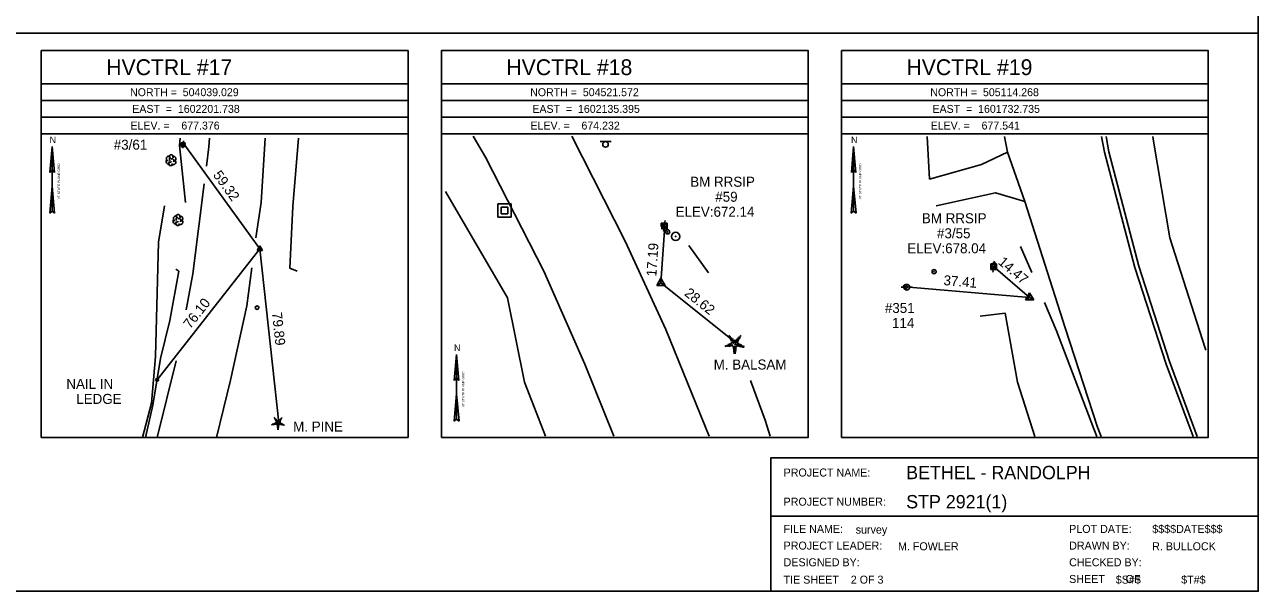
# Model space of a CAD drawing. Extents: x 1598730 to 1599370, y 501440 to 502728.
# Drawn here: x 1598999.5 to 1599369.5, y 501873 to 502042.9 of the extents above; entities that cross this region are included whole.
import ezdxf

# ---------------------------------------------------------------- set-up
doc = ezdxf.new("R2010")
doc.units = 0
for name, color, linetype in [('C_C', 7, 'Continuous'), ('CBP', 7, 'Continuous'), ('CPBM', 7, 'Continuous'), ('CPSM', 7, 'Continuous'), ('Default', 7, 'Continuous'), ('DS', 7, 'Continuous'), ('L_C', 7, 'Continuous'), ('LABL', 7, 'Continuous'), ('LARO', 7, 'Continuous'), ('LAWA', 7, 'Continuous'), ('LFNC', 7, 'Continuous'), ('LTC', 7, 'Continuous'), ('LTD', 7, 'Continuous'), ('MPIR', 7, 'Continuous'), ('NBL1', 7, 'Continuous'), ('NBL2', 7, 'Continuous'), ('NNA_P', 7, 'Continuous'), ('PET', 7, 'Continuous'), ('RDG', 7, 'Continuous'), ('RDP', 7, 'Continuous'), ('RGP', 7, 'Continuous'), ('RGR', 7, 'Continuous'), ('SSGN', 7, 'Continuous'), ('U_C', 7, 'Continuous'), ('UP', 7, 'Continuous'), ('UPGW', 7, 'Continuous'), ('UTMH', 7, 'Continuous')]:
    doc.layers.add(name, color=color, linetype=linetype)

msp = doc.modelspace()

# ---------------------------------------------------------------- linework, layer by layer
at = {"layer": 'CBP'}
for centre, radius in [((1599047.25, 502007.23), 0.41), ((1599047.25, 502007.23), 0.0547), ((1599191.49, 501982.63), 0.625), ((1599191.49, 501982.63), 0.0833), ((1599289.96, 501970.55), 0.625), ((1599289.96, 501970.55), 0.0833), ((1599263.66, 501964.32), 0.625), ((1599263.66, 501964.32), 0.0833), ((1599212.73, 501947.63), 0.625), ((1599212.73, 501947.63), 0.0833), ((1599039.25, 501936.41), 0.41), ((1599039.25, 501936.41), 0.0547), ((1599075.78, 501923.58), 0.41), ((1599075.78, 501923.58), 0.0547)]:
    msp.add_circle(centre, radius, dxfattribs=at)
at = {"layer": 'CPBM'}
for p, q in [((1599190.44, 501982.37), (1599190.44, 501983.37)), ((1599190.44, 501983.37), (1599191.44, 501983.37)), ((1599191.44, 501983.37), (1599191.44, 501982.37)), ((1599191.44, 501982.37), (1599190.44, 501982.37)), ((1599190.94, 501982.87), (1599190.94, 501982.87)), ((1599190.94, 501982.87), (1599190.94, 501982.87)), ((1599289.8, 501970.38), (1599289.8, 501971.38)), ((1599289.8, 501971.38), (1599290.8, 501971.38)), ((1599290.8, 501970.38), (1599289.8, 501970.38)), ((1599290.31, 501970.88), (1599290.31, 501970.88)), ((1599290.31, 501970.88), (1599290.31, 501970.88)), ((1599290.8, 501971.38), (1599290.8, 501970.38)), ((1599075.46, 501923.34), (1599075.46, 501923.99)), ((1599075.46, 501923.99), (1599076.12, 501923.99)), ((1599076.12, 501923.34), (1599075.46, 501923.34)), ((1599075.79, 501923.66), (1599075.79, 501923.66)), ((1599075.79, 501923.66), (1599075.79, 501923.66)), ((1599076.12, 501923.99), (1599076.12, 501923.34))]:
    msp.add_line(p, q, dxfattribs=at)
at = {"layer": 'CPSM'}
for p, q in [((1599069.25, 501975.22), (1599070.07, 501976.64)), ((1599070.89, 501975.22), (1599070.07, 501976.64)), ((1599070.07, 501975.69), (1599070.07, 501976.64)), ((1599069.25, 501975.22), (1599070.07, 501975.69)), ((1599069.25, 501975.22), (1599070.89, 501975.22)), ((1599070.07, 501975.69), (1599070.07, 501975.69)), ((1599070.07, 501975.69), (1599070.89, 501975.22)), ((1599189.11, 501964.75), (1599190.36, 501966.92)), ((1599189.11, 501964.75), (1599190.36, 501965.47)), ((1599189.11, 501964.75), (1599191.61, 501964.75)), ((1599191.61, 501964.75), (1599190.36, 501966.92)), ((1599190.36, 501965.47), (1599190.36, 501966.92)), ((1599190.36, 501965.47), (1599190.36, 501965.47)), ((1599190.36, 501965.47), (1599191.61, 501964.75)), ((1599299.69, 501960.39), (1599300.94, 501962.56)), ((1599299.69, 501960.39), (1599300.94, 501961.11)), ((1599302.19, 501960.39), (1599300.94, 501962.56)), ((1599300.94, 501961.11), (1599300.94, 501962.56)), ((1599300.94, 501961.11), (1599300.94, 501961.11)), ((1599300.94, 501961.11), (1599302.19, 501960.39)), ((1599299.69, 501960.39), (1599302.19, 501960.39))]:
    msp.add_line(p, q, dxfattribs=at)
at = {"layer": 'Default'}
for p, q in [((1599070.07, 501975.69), (1599047.25, 502007.23)), ((1599190.36, 501965.47), (1599191.49, 501982.63)), ((1599070.07, 501975.69), (1599039.25, 501936.41)), ((1599075.78, 501923.58), (1599070.07, 501975.69)), ((1599300.94, 501961.11), (1599289.96, 501970.55)), ((1599212.73, 501947.63), (1599190.36, 501965.47)), ((1599263.66, 501964.32), (1599300.94, 501961.11))]:
    msp.add_line(p, q, dxfattribs=at)
at = {"layer": 'DS'}
for p, q in [((1599141.47, 501989.17), (1599145.47, 501989.17)), ((1599141.47, 501985.17), (1599141.47, 501989.17)), ((1599142.47, 501986.17), (1599142.47, 501988.17)), ((1599142.47, 501988.17), (1599144.47, 501988.17)), ((1599143.47, 501987.17), (1599143.47, 501987.17)), ((1599143.47, 501987.17), (1599143.47, 501987.17)), ((1599144.47, 501988.17), (1599144.47, 501986.17)), ((1599145.47, 501989.17), (1599145.47, 501985.17)), ((1599145.47, 501985.17), (1599141.47, 501985.17)), ((1599144.47, 501986.17), (1599142.47, 501986.17))]:
    msp.add_line(p, q, dxfattribs=at)
at = {"layer": 'LABL'}
for points in [[(1599047.82, 501989.57), (1599045.99, 502006.66), (1599046.18, 502008.9)], [(1599302.46, 501919.47), (1599297.26, 501935.71), (1599293.6, 501956.43), (1599286.07, 501955.55)]]:
    msp.add_lwpolyline(points, dxfattribs=at)
at = {"layer": 'LARO'}
msp.add_lwpolyline([(1599035.77, 501919.18), (1599037.98, 501928.82), (1599040.31, 501942.87), (1599043.1, 501954.27), (1599045.76, 501969), (1599044.87, 501969.59)], dxfattribs=at)
at = {"layer": 'LAWA'}
for points in [[(1599353.82, 501945.32), (1599353.58, 501945.95), (1599343, 501979.03), (1599338.14, 502008.01), (1599337.86, 502009.44)], [(1599155.76, 501919.52), (1599149.43, 501935.77), (1599144.39, 501961.06), (1599125.75, 501992.92)], [(1599034.84, 501919.18), (1599037.58, 501929.42), (1599038.81, 501943.43), (1599039.71, 501977.67), (1599041.45, 501988.65)], [(1599204.63, 501968.54), (1599198.73, 501976.75)], [(1599223.16, 501919.52), (1599221.59, 501924.37), (1599217.24, 501936.19)]]:
    msp.add_lwpolyline(points, dxfattribs=at)
at = {"layer": 'LFNC'}
msp.add_lwpolyline([(1599081.27, 501969.02), (1599079.06, 501969.92), (1599079.93, 501988.37), (1599081.63, 502008.9)], dxfattribs=at)
at = {"layer": 'LTC'}
for p, q in [((1599209.66, 501946.75), (1599209.82, 501946.29)), ((1599210.12, 501946.97), (1599210.33, 501946.32)), ((1599210.58, 501947.19), (1599210.85, 501946.35)), ((1599210.63, 501949.47), (1599210.99, 501949.73)), ((1599210.84, 501949.01), (1599211.37, 501949.39)), ((1599211.03, 501947.4), (1599211.36, 501946.38)), ((1599211.05, 501948.54), (1599211.75, 501949.05)), ((1599211.26, 501948.08), (1599212.14, 501948.72)), ((1599211.49, 501947.62), (1599212.5, 501948.36)), ((1599211.49, 501947.62), (1599211.87, 501946.43)), ((1599213.1, 501946.43), (1599211.87, 501946.43)), ((1599212.5, 501948.36), (1599213.49, 501947.63)), ((1599212.92, 501948.67), (1599213.73, 501948.08)), ((1599213.49, 501947.63), (1599213.1, 501946.43)), ((1599213.29, 501949.02), (1599213.97, 501948.52)), ((1599213.93, 501947.36), (1599213.59, 501946.32)), ((1599213.66, 501949.37), (1599214.21, 501948.97)), ((1599214.03, 501949.71), (1599214.45, 501949.41)), ((1599214.38, 501947.11), (1599214.09, 501946.23)), ((1599214.82, 501946.86), (1599214.58, 501946.13)), ((1599215.26, 501946.61), (1599215.08, 501946.04)), ((1599213.06, 501945.93), (1599211.92, 501945.93)), ((1599212.98, 501945.43), (1599211.99, 501945.43)), ((1599212.9, 501944.93), (1599212.07, 501944.93)), ((1599212.81, 501944.43), (1599212.14, 501944.43)), ((1599074.31, 501924.95), (1599074.54, 501925.12)), ((1599074.45, 501924.65), (1599074.79, 501924.9)), ((1599074.58, 501924.34), (1599075.05, 501924.68)), ((1599074.72, 501924.04), (1599075.3, 501924.45)), ((1599074.87, 501923.74), (1599075.53, 501924.22)), ((1599075.53, 501924.22), (1599076.19, 501923.74)), ((1599075.81, 501924.42), (1599076.34, 501924.04)), ((1599076.05, 501924.65), (1599076.5, 501924.33)), ((1599076.29, 501924.88), (1599076.66, 501924.62)), ((1599076.54, 501925.11), (1599076.81, 501924.91)), ((1599073.67, 501923.17), (1599073.77, 501922.86)), ((1599073.97, 501923.31), (1599074.11, 501922.88)), ((1599074.27, 501923.45), (1599074.45, 501922.9)), ((1599074.57, 501923.59), (1599074.79, 501922.92)), ((1599074.87, 501923.74), (1599075.12, 501922.95)), ((1599075.93, 501922.95), (1599075.12, 501922.95)), ((1599075.9, 501922.63), (1599075.15, 501922.63)), ((1599075.85, 501922.3), (1599075.2, 501922.3)), ((1599075.79, 501921.97), (1599075.25, 501921.97)), ((1599075.74, 501921.64), (1599075.3, 501921.64)), ((1599076.19, 501923.74), (1599075.93, 501922.95)), ((1599076.47, 501923.57), (1599076.25, 501922.88)), ((1599076.77, 501923.4), (1599076.58, 501922.82)), ((1599077.06, 501923.24), (1599076.9, 501922.76)), ((1599077.35, 501923.07), (1599077.23, 501922.7))]:
    msp.add_line(p, q, dxfattribs=at)
at = {"layer": 'LTD'}
for p, q in [((1599043.4, 502002.32), (1599043.4, 502002.32)), ((1599043.4, 502002.32), (1599043.4, 502002.32)), ((1599045.49, 501984.38), (1599045.49, 501984.38)), ((1599045.49, 501984.38), (1599045.49, 501984.38))]:
    msp.add_line(p, q, dxfattribs=at)
for centre in [(1599043.43, 502003.26), (1599045.52, 501985.32)]:
    msp.add_arc(centre, 0.687, 335.5272, 180.9563, dxfattribs=at)
for centre, major_axis, ratio, start_param, end_param in [((1599042.68, 502001.86), (0.383, -0.683), 0.959034, 3.141593, 6.283185), ((1599042.88, 502002.76), (0.794, -0.336), 0.895232, 1.570796, 4.712389), ((1599043.09, 502001.83), (-0.41, -0.055), 0.423636, 0, 3.141593), ((1599043.26, 502002.62), (-0.137, -0.519), 0.645439, 3.141593, 6.283185), ((1599043.72, 502002.21), (-0.328, 0.437), 0.989748, 3.141593, 6.283185), ((1599044.05, 502001.78), (-0.715, 0.52), 0.841452, 1.570796, 4.712389), ((1599044.08, 502002.71), (-0.748, -0.317), 0.949671, 1.570796, 4.712389), ((1599043.4, 502001.34), (0.174, 0.696), 0.942809, 1.570796, 4.712389), ((1599044.78, 501983.91), (0.383, -0.683), 0.959034, 3.141593, 6.283185), ((1599044.97, 501984.81), (0.794, -0.336), 0.895232, 1.570796, 4.712389), ((1599045.49, 501983.39), (0.174, 0.696), 0.942809, 1.570796, 4.712389), ((1599045.19, 501983.89), (-0.41, -0.055), 0.423636, 0, 3.141593), ((1599045.35, 501984.68), (-0.137, -0.519), 0.645439, 3.141593, 6.283185), ((1599045.82, 501984.27), (-0.328, 0.437), 0.989748, 3.141593, 6.283185), ((1599046.15, 501983.83), (-0.715, 0.52), 0.841452, 1.570796, 4.712389), ((1599046.17, 501984.76), (-0.748, -0.317), 0.949671, 1.570796, 4.712389)]:
    msp.add_ellipse(centre, major_axis=major_axis, ratio=ratio, start_param=start_param, end_param=end_param, dxfattribs=at)
at = {"layer": 'MPIR'}
for radius in [0.625, 0.0833]:
    msp.add_circle((1599192.37, 501980.8), radius, dxfattribs=at)
at = {"layer": 'NBL1'}
msp.add_line((1599223.28, 501895.51), (1599369.53, 501895.51), dxfattribs=at)
msp.add_lwpolyline([(1598729.53, 501873.01), (1599369.53, 501873.01), (1599369.53, 502293.01), (1598729.53, 502293.01)], close=True, dxfattribs=at)
msp.add_lwpolyline([(1599369.53, 501913.01), (1599223.28, 501913.01), (1599223.28, 501873.01)], dxfattribs=at)
at = {"layer": 'NBL2'}
for p, q in [((1598729.53, 502040.34), (1599369.53, 502040.34)), ((1599114.53, 502025.18), (1599004.53, 502025.18)), ((1599234.53, 502025.18), (1599124.53, 502025.18)), ((1599354.53, 502025.18), (1599244.53, 502025.18)), ((1599114.53, 502020.18), (1599004.53, 502020.18)), ((1599234.53, 502020.18), (1599124.53, 502020.18)), ((1599354.53, 502020.18), (1599244.53, 502020.18)), ((1599114.53, 502015.18), (1599004.53, 502015.18)), ((1599234.53, 502015.18), (1599124.53, 502015.18)), ((1599354.53, 502015.18), (1599244.53, 502015.18)), ((1599114.53, 502010.18), (1599004.53, 502010.18)), ((1599234.53, 502010.18), (1599124.53, 502010.18)), ((1599354.53, 502010.18), (1599244.53, 502010.18))]:
    msp.add_line(p, q, dxfattribs=at)
for points in [[(1599004.53, 501919.18), (1599114.53, 501919.18), (1599114.53, 502035.18), (1599004.53, 502035.18)], [(1599124.53, 501919.18), (1599234.53, 501919.18), (1599234.53, 502035.18), (1599124.53, 502035.18)], [(1599244.53, 501919.18), (1599354.53, 501919.18), (1599354.53, 502035.18), (1599244.53, 502035.18)]]:
    msp.add_lwpolyline(points, close=True, dxfattribs=at)
at = {"layer": 'NNA_P'}
for p, q in [((1599007.09, 501998.59), (1599007.79, 502006.38)), ((1599007.79, 501987.01), (1599007.79, 502006.38)), ((1599008.48, 501998.59), (1599007.79, 502006.38)), ((1599247.47, 501998.59), (1599248.16, 502006.38)), ((1599248.16, 501987.01), (1599248.16, 502006.38)), ((1599248.85, 501998.59), (1599248.16, 502006.38)), ((1599007.09, 501998.59), (1599007.79, 501999.36)), ((1599008.48, 501998.59), (1599007.79, 501999.36)), ((1599247.47, 501998.59), (1599248.16, 501999.36)), ((1599248.86, 501998.59), (1599248.16, 501999.36)), ((1599007.79, 501994.53), (1599007.07, 501986.37)), ((1599007.79, 501994.53), (1599008.51, 501986.37)), ((1599248.16, 501994.53), (1599247.44, 501986.37)), ((1599248.16, 501994.53), (1599248.88, 501986.37)), ((1599007.79, 501987.01), (1599007.07, 501986.37)), ((1599007.79, 501987.01), (1599008.51, 501986.37)), ((1599248.16, 501987.01), (1599247.44, 501986.37)), ((1599248.16, 501987.01), (1599248.88, 501986.37)), ((1599128.39, 501936.25), (1599129.08, 501944.04)), ((1599129.09, 501924.67), (1599129.08, 501944.04)), ((1599129.78, 501936.25), (1599129.08, 501944.04)), ((1599128.39, 501936.25), (1599129.09, 501937.02)), ((1599129.78, 501936.25), (1599129.09, 501937.02)), ((1599129.09, 501932.2), (1599128.37, 501924.03)), ((1599129.09, 501932.2), (1599129.81, 501924.03)), ((1599129.09, 501924.67), (1599128.37, 501924.03)), ((1599129.09, 501924.67), (1599129.81, 501924.03))]:
    msp.add_line(p, q, dxfattribs=at)
at = {"layer": 'PET'}
for points in [[(1599176.24, 501919.52), (1599167.53, 501941.08), (1599155.21, 501968.99), (1599137.74, 502003.21), (1599134.05, 502009.54)], [(1599204.78, 501919.52), (1599191.87, 501951.52), (1599179.61, 501977.97), (1599163.65, 502009.54)], [(1599322.37, 501919.47), (1599321.26, 501922.28), (1599311.63, 501952.05), (1599299.52, 501989.9), (1599294.3, 502004.65), (1599293.36, 502009.44)], [(1599349.95, 501919.47), (1599341.87, 501941.13), (1599332.53, 501970.1), (1599323.4, 502004.7), (1599322.52, 502009.44)], [(1599054.08, 502000.54), (1599054.81, 502006.3), (1599054.99, 502008.9)], [(1599068.87, 501979.06), (1599070.43, 501989.61), (1599071.62, 502008.9)], [(1599047.94, 501957.45), (1599050.01, 501968.19), (1599053.41, 501995.17)], [(1599057.11, 501919.18), (1599061.31, 501936.33), (1599066.19, 501958.65), (1599067.63, 501970.03)], [(1599039.32, 501919.18), (1599044.98, 501942.11)]]:
    msp.add_lwpolyline(points, dxfattribs=at)
at = {"layer": 'RDG'}
msp.add_lwpolyline([(1599270.87, 501996.64), (1599270.22, 502009.44)], dxfattribs=at)
at = {"layer": 'RDP'}
for points in [[(1599270.87, 501996.64), (1599286.53, 502000.97), (1599294.3, 502004.65)], [(1599299.52, 501989.9), (1599290.7, 501992.53), (1599272.91, 501988.61)]]:
    msp.add_lwpolyline(points, dxfattribs=at)
at = {"layer": 'RGP'}
msp.add_line((1599194.79, 501979.43), (1599194.79, 501979.43), dxfattribs=at)
for radius in [1.25, 0.0833]:
    msp.add_circle((1599194.79, 501979.43), radius, dxfattribs=at)
at = {"layer": 'RGR'}
for points in [[(1599351.17, 501919.47), (1599342.89, 501941.89), (1599333.65, 501970.56), (1599324.73, 502004.82), (1599323.88, 502009.44)], [(1599301.59, 501968.61), (1599298.24, 501976.45)], [(1599321.1, 501919.47), (1599320.22, 501921.72), (1599309.05, 501951.14), (1599305.44, 501959.59)]]:
    msp.add_lwpolyline(points, dxfattribs=at)
at = {"layer": 'SSGN'}
for p, q in [((1599172.11, 502007.86), (1599175.44, 502007.86)), ((1599173.75, 502007.03), (1599173.75, 502007.03))]:
    msp.add_line(p, q, dxfattribs=at)
msp.add_circle((1599173.75, 502007.03), 0.833, dxfattribs=at)
at = {"layer": 'UP'}
for p, q in [((1599046.5, 502006.42), (1599046.5, 502007.51)), ((1599046.5, 502007.51), (1599047.6, 502007.51)), ((1599047.6, 502006.42), (1599046.5, 502006.42)), ((1599046.89, 502005.87), (1599047.05, 502006.42)), ((1599047.21, 502008.06), (1599047.05, 502007.51)), ((1599047.05, 502006.97), (1599047.05, 502006.97)), ((1599047.6, 502007.51), (1599047.6, 502006.42)), ((1599190.6, 501981.75), (1599190.6, 501983.42)), ((1599190.6, 501983.42), (1599192.26, 501983.42)), ((1599191.68, 501984.25), (1599191.43, 501983.42)), ((1599192.26, 501983.42), (1599192.26, 501981.75)), ((1599192.26, 501981.75), (1599190.6, 501981.75)), ((1599191.18, 501980.92), (1599191.43, 501981.75)), ((1599191.43, 501982.59), (1599191.43, 501982.59)), ((1599289.3, 501969.5), (1599289.3, 501971.17)), ((1599289.3, 501971.17), (1599290.97, 501971.17)), ((1599290.97, 501969.5), (1599289.3, 501969.5)), ((1599289.88, 501968.67), (1599290.13, 501969.5)), ((1599290.38, 501972), (1599290.13, 501971.17)), ((1599290.13, 501970.34), (1599290.13, 501970.34)), ((1599290.97, 501971.17), (1599290.97, 501969.5)), ((1599262.44, 501964.2), (1599263.26, 501964.2)), ((1599264.1, 501964.2), (1599264.1, 501964.2)), ((1599265.76, 501964.2), (1599264.93, 501964.2)), ((1599264.93, 501964.2), (1599264.93, 501964.2)), ((1599265.76, 501964.2), (1599265.76, 501964.2))]:
    msp.add_line(p, q, dxfattribs=at)
for centre, radius in [((1599047.05, 502006.97), 0.547), ((1599191.43, 501982.59), 0.833), ((1599290.13, 501970.34), 0.833), ((1599264.1, 501964.2), 0.833)]:
    msp.add_circle(centre, radius, dxfattribs=at)
at = {"layer": 'UPGW'}
for radius in [0.625, 0.0833]:
    msp.add_circle((1599272.29, 501968.86), radius, dxfattribs=at)
at = {"layer": 'UTMH'}
for p, q in [((1599069.26, 501958.07), (1599069.26, 501958.07)), ((1599069.8, 501958.07), (1599069.8, 501958.07))]:
    msp.add_line(p, q, dxfattribs=at)
msp.add_circle((1599069.26, 501958.07), 0.547, dxfattribs=at)

# ---------------------------------------------------------------- texts
at = {"layer": 'C_C'}
for s, p in [('NAIL IN', (1599012.03, 501933.71)), ('LEDGE', (1599015.02, 501929.21))]:
    msp.add_text(s, height=3, dxfattribs=at).set_placement(p)
at = {"layer": 'Default'}
for s, rotation, p in [('59.32', 305.8949, (1599055.89, 501997.84)), ('17.19', 86.2208, (1599188.98, 501967.36)), ('14.47', 319.3244, (1599291.28, 501971.39)), ('37.41', 355.0796, (1599275.01, 501964.85)), ('28.62', 321.4188, (1599197.17, 501961.96)), ('76.10', 51.8857, (1599049.21, 501951.53)), ('79.89', 276.2537, (1599073.68, 501956.56))]:
    msp.add_text(s, height=3, rotation=rotation, dxfattribs=at).set_placement(p)
at = {"layer": 'L_C'}
for s, p in [('M. BALSAM', (1599206.18, 501939.52)), ('M. PINE', (1599080.06, 501920.93))]:
    msp.add_text(s, height=3, dxfattribs=at).set_placement(p)
at = {"layer": 'LTC'}
for height, p in [(1.04, (1599212.38, 501947.37)), (0.681, (1599075.46, 501923.57))]:
    msp.add_text('.', height=height, rotation=270, dxfattribs=at).set_placement(p)
at = {"layer": 'NBL1'}
for s, height, p in [('PROJECT NAME:', 2.4, (1599227.15, 501907.44)), ('BETHEL - RANDOLPH         ', 4, (1599263.92, 501906.64)), ('STP 2921(1)               ', 4, (1599263.92, 501897.89)), ('PROJECT NUMBER:', 2.4, (1599227.15, 501898.69)), ('FILE NAME:', 2.4, (1599227.15, 501890.52)), ('survey                    ', 2.4, (1599248.78, 501890.32)), ('PLOT DATE:', 2.4, (1599312.8, 501890.52)), ('$$$$DATE$$$', 2.4, (1599337.73, 501890.52)), ('PROJECT LEADER:', 2.4, (1599227.15, 501885.52)), ('M. FOWLER           ', 2.4, (1599261.47, 501885.32)), ('DRAWN BY:', 2.4, (1599312.8, 501885.52)), ('R. BULLOCK   ', 2.4, (1599337.7, 501885.32)), ('DESIGNED BY:', 2.4, (1599227.15, 501880.52)), ('CHECKED BY:', 2.4, (1599312.8, 501880.52)), ('TIE SHEET    2 OF 3               ', 2.4, (1599227.15, 501875.32)), ('SHEET       OF', 2.4, (1599312.8, 501875.52)), ('$S#$ ', 2.4, (1599326.78, 501875.32)), ('$T#$   ', 2.4, (1599346.4, 501875.32))]:
    msp.add_text(s, height=height, dxfattribs=at).set_placement(p)
at = {"layer": 'NBL2'}
for s, height, p in [('     HVCTRL #17    ', 4.75, (1599015.18, 502027.8)), ('     HVCTRL #18    ', 4.75, (1599135.18, 502027.8)), ('     HVCTRL #19    ', 4.75, (1599255.18, 502027.8)), ('NORTH =  504039.029 ', 2.375, (1599031.15, 502021.49)), ('NORTH =  504521.572 ', 2.375, (1599151.15, 502021.49)), ('NORTH =  505114.268 ', 2.375, (1599271.15, 502021.49)), ('EAST  =  1602201.738', 2.375, (1599031.81, 502016.49)), ('EAST  =  1602135.395', 2.375, (1599151.81, 502016.49)), ('EAST  =  1601732.735', 2.375, (1599271.81, 502016.49)), ('ELEV. =    677.376  ', 2.375, (1599031.26, 502011.49)), ('ELEV. =    674.232  ', 2.375, (1599151.26, 502011.49)), ('ELEV. =    677.541  ', 2.375, (1599271.26, 502011.49))]:
    msp.add_text(s, height=height, dxfattribs=at).set_placement(p)
at = {"layer": 'NNA_P'}
for p in [(1599007.03, 502007.4), (1599247.4, 502007.4), (1599128.32, 501945.06)]:
    msp.add_text('N', height=1.97, dxfattribs=at).set_placement(p)
for p in [(1599010.14, 501990.57), (1599250.51, 501990.57), (1599131.44, 501928.23)]:
    msp.add_text('VT STATE PLANE GRID', height=0.7, rotation=90.0204, dxfattribs=at).set_placement(p)
at = {"layer": 'U_C'}
for s, p in [('#3/61', (1599026.26, 502005.44)), ('BM RRSIP', (1599199.15, 501994.33)), ('#59', (1599206.66, 501989.83)), ('ELEV:672.14', (1599194.76, 501985.33)), ('BM RRSIP', (1599268.63, 501983.38)), ('#3/55', (1599273.17, 501978.88)), ('ELEV:678.04', (1599264.24, 501974.38)), ('#351', (1599257.53, 501956.48)), ('114', (1599259.67, 501951.98))]:
    msp.add_text(s, height=3, dxfattribs=at).set_placement(p)

doc.saveas('drawing.dxf')
